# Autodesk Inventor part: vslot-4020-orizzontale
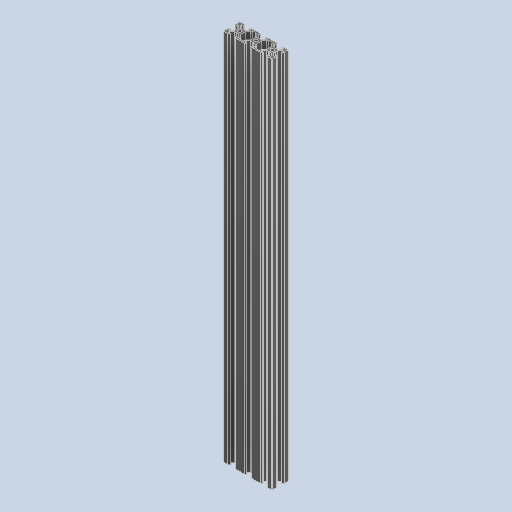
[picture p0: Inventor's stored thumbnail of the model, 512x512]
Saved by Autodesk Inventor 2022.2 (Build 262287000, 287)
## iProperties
Created: 2024-10
Part Number: vslot-4020-orizzontale
Material: Alluminio 6061
Document SubType Name: Modeling
Designer: 18907419
Density: 2.7 g/cm^3
Appearance: Default
Author: 18907419
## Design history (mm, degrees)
feature "Solido47"
node "Solido1"
